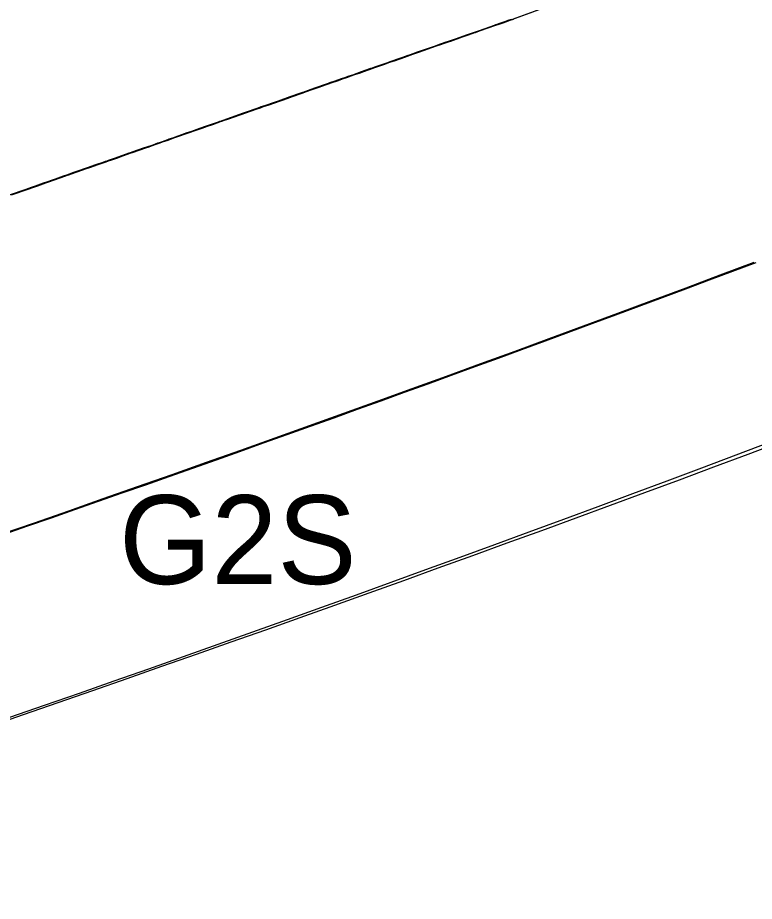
# Model space of a CAD drawing. Extents: x 0 to 512122, y 0 to 6212554.
# Drawn here: x 511630.09 to 511640.46, y 6211385.17 to 6211397.6 of the extents above; entities that cross this region are included whole.
import ezdxf

# ---------------------------------------------------------------- set-up
doc = ezdxf.new("R2010")
doc.units = 0
for name, color, linetype in [('_Paths', 7, 'Continuous'), ('_S1_rabarber', 7, 'Continuous'), ('Tilgængelighed-1', 7, 'Continuous'), ('TV_U_AFM_Symbl_Gul', 7, 'Continuous'), ('TV_U_LYS_Nyx330-Trafiksti-x2', 7, 'Continuous')]:
    doc.layers.add(name, color=color, linetype=linetype)

msp = doc.modelspace()

# ---------------------------------------------------------------- linework, layer by layer
at = {"layer": '_Paths'}
for centre, radius, start, end in [((511490.629, 6211792.585), 425.663, 281.76765, 290.60954), ((511492.968, 6211783.33), 418.626, 281.73735, 290.80486), ((511490.629, 6211792.585), 428.163, 281.76765, 290.60954)]:
    msp.add_arc(centre, radius, start, end, dxfattribs=at)
at = {"layer": '_S1_rabarber'}
for points in [[(511651.978, 6211402.756), (511652.648, 6211403.165), (511654.696, 6211404.619), (511652.478, 6211403.495), (511648.686, 6211401.828), (511637.043, 6211397.572)], [(511648.686, 6211401.828), (511637.066, 6211397.581), (511637.066, 6211397.58), (511637.021, 6211397.564), (511636.972, 6211397.547), (511636.906, 6211397.524), (511636.864, 6211397.509), (511636.849, 6211397.504), (511636.829, 6211397.497), (511636.696, 6211397.45), (511636.602, 6211397.417), (511636.532, 6211397.393), (511636.52, 6211397.389), (511636.433, 6211397.358), (511636.347, 6211397.328), (511636.181, 6211397.27), (511636.149, 6211397.259), (511636.068, 6211397.231), (511636.056, 6211397.226), (511635.983, 6211397.201), (511635.731, 6211397.113), (511635.719, 6211397.108), (511635.648, 6211397.084), (511635.537, 6211397.045), (511635.468, 6211397.021), (511635.39, 6211396.993), (511635.359, 6211396.982), (511635.325, 6211396.971), (511635.242, 6211396.941), (511635.142, 6211396.907), (511635.112, 6211396.896), (511635.089, 6211396.888), (511634.958, 6211396.842), (511634.896, 6211396.82), (511634.832, 6211396.798), (511634.78, 6211396.78), (511634.719, 6211396.758), (511634.673, 6211396.742), (511634.585, 6211396.711), (511634.511, 6211396.686), (511634.5, 6211396.682), (511634.475, 6211396.673), (511634.434, 6211396.659), (511634.327, 6211396.621), (511634.3, 6211396.612), (511634.246, 6211396.593), (511634.136, 6211396.554), (511634.128, 6211396.551), (511634.088, 6211396.537), (511633.953, 6211396.49), (511633.916, 6211396.477), (511633.825, 6211396.445), (511633.771, 6211396.426), (511633.719, 6211396.408), (511633.611, 6211396.37), (511633.545, 6211396.348), (511633.501, 6211396.332), (511633.458, 6211396.317), (511633.363, 6211396.284), (511633.295, 6211396.26), (511633.23, 6211396.237), (511633.123, 6211396.2), (511633.058, 6211396.177), (511632.969, 6211396.146), (511632.961, 6211396.143), (511632.958, 6211396.142), (511632.956, 6211396.141), (511632.83, 6211396.097), (511632.759, 6211396.072), (511632.68, 6211396.044), (511632.568, 6211396.005), (511632.503, 6211395.983), (511632.299, 6211395.911), (511632.249, 6211395.893), (511632.205, 6211395.878), (511632.125, 6211395.85), (511632.088, 6211395.837), (511632.02, 6211395.813), (511631.921, 6211395.779), (511631.902, 6211395.772), (511631.794, 6211395.734), (511631.702, 6211395.702), (511631.684, 6211395.696), (511631.529, 6211395.642), (511631.493, 6211395.629), (511631.395, 6211395.595), (511631.363, 6211395.583), (511631.352, 6211395.58), (511631.317, 6211395.567), (511631.201, 6211395.527), (511631.112, 6211395.495), (511631.041, 6211395.471), (511631.002, 6211395.457), (511630.906, 6211395.424), (511630.805, 6211395.388), (511630.773, 6211395.377), (511630.761, 6211395.373), (511630.59, 6211395.313), (511630.538, 6211395.295), (511630.48, 6211395.274), (511630.366, 6211395.235), (511630.311, 6211395.215), (511630.232, 6211395.188), (511629.998, 6211395.105)], [(511637.066, 6211397.58), (511637.021, 6211397.564), (511636.972, 6211397.547), (511636.906, 6211397.524), (511636.864, 6211397.509), (511636.849, 6211397.504), (511636.829, 6211397.497), (511636.696, 6211397.45), (511636.602, 6211397.417), (511636.532, 6211397.393), (511636.52, 6211397.389), (511636.433, 6211397.358), (511636.347, 6211397.328), (511636.181, 6211397.27), (511636.149, 6211397.259), (511636.068, 6211397.231), (511636.056, 6211397.226), (511635.983, 6211397.201), (511635.731, 6211397.113), (511635.719, 6211397.108), (511635.648, 6211397.084), (511635.537, 6211397.045), (511635.468, 6211397.021), (511635.39, 6211396.993), (511635.359, 6211396.982), (511635.325, 6211396.971), (511635.242, 6211396.941), (511635.142, 6211396.907), (511635.112, 6211396.896), (511635.089, 6211396.888), (511634.958, 6211396.842), (511634.896, 6211396.82), (511634.832, 6211396.798), (511634.78, 6211396.78), (511634.719, 6211396.758), (511634.673, 6211396.742), (511634.585, 6211396.711), (511634.511, 6211396.686), (511634.5, 6211396.682), (511634.475, 6211396.673), (511634.434, 6211396.659), (511634.327, 6211396.621), (511634.3, 6211396.612), (511634.246, 6211396.593), (511634.136, 6211396.554), (511634.128, 6211396.551), (511634.088, 6211396.537), (511633.953, 6211396.49), (511633.916, 6211396.477), (511633.825, 6211396.445), (511633.771, 6211396.426), (511633.719, 6211396.408), (511633.611, 6211396.37), (511633.545, 6211396.348), (511633.501, 6211396.332), (511633.458, 6211396.317), (511633.363, 6211396.284), (511633.295, 6211396.26), (511633.23, 6211396.237), (511633.123, 6211396.2), (511633.058, 6211396.177), (511632.969, 6211396.146), (511632.961, 6211396.143), (511632.958, 6211396.142), (511632.956, 6211396.141), (511632.83, 6211396.097), (511632.759, 6211396.072), (511632.68, 6211396.044), (511632.568, 6211396.005), (511632.503, 6211395.983), (511632.299, 6211395.911), (511632.249, 6211395.893), (511632.205, 6211395.878), (511632.125, 6211395.85), (511632.088, 6211395.837), (511632.02, 6211395.813), (511631.921, 6211395.779), (511631.902, 6211395.772), (511631.794, 6211395.734), (511631.702, 6211395.702), (511631.684, 6211395.696), (511631.529, 6211395.642), (511631.493, 6211395.629), (511631.395, 6211395.595), (511631.363, 6211395.583), (511631.352, 6211395.58), (511631.317, 6211395.567), (511631.201, 6211395.527), (511631.112, 6211395.495), (511631.041, 6211395.471), (511631.002, 6211395.457), (511630.906, 6211395.424), (511630.805, 6211395.388), (511630.773, 6211395.377), (511630.761, 6211395.373), (511630.59, 6211395.313), (511630.538, 6211395.295), (511630.48, 6211395.274), (511630.366, 6211395.235), (511630.311, 6211395.215), (511630.232, 6211395.188), (511629.998, 6211395.105)]]:
    msp.add_lwpolyline(points, dxfattribs=at)
msp.add_arc((511490.655, 6211792.581), 425.663, 287.57872, 290.60954, dxfattribs=at)
msp.add_arc((511490.655, 6211792.581), 425.663, 287.57872, 290.60954, dxfattribs=at)
at = {"layer": 'Tilgængelighed-1'}
msp.add_lwpolyline([(511629.972, 6211395.109), (511630.206, 6211395.192), (511630.285, 6211395.219), (511630.34, 6211395.239), (511630.454, 6211395.278), (511630.512, 6211395.299), (511630.564, 6211395.317), (511630.621, 6211395.337), (511630.735, 6211395.377), (511630.747, 6211395.381), (511630.779, 6211395.392), (511630.88, 6211395.428), (511630.976, 6211395.461), (511631.015, 6211395.475), (511631.086, 6211395.499), (511631.175, 6211395.531), (511631.204, 6211395.541), (511631.291, 6211395.571), (511631.326, 6211395.584), (511631.337, 6211395.587), (511631.369, 6211395.599), (511631.467, 6211395.633), (511631.503, 6211395.646), (511631.658, 6211395.7), (511631.676, 6211395.706), (511631.768, 6211395.738), (511631.876, 6211395.776), (511631.895, 6211395.783), (511631.994, 6211395.817), (511632.062, 6211395.841), (511632.099, 6211395.854), (511632.179, 6211395.882), (511632.223, 6211395.897), (511632.273, 6211395.915), (511632.477, 6211395.987), (511632.542, 6211396.009), (511632.654, 6211396.048), (511632.733, 6211396.076), (511632.804, 6211396.101), (511632.93, 6211396.145), (511632.932, 6211396.146), (511632.935, 6211396.147), (511632.943, 6211396.15), (511633.032, 6211396.181), (511633.097, 6211396.204), (511633.204, 6211396.241), (511633.269, 6211396.264), (511633.337, 6211396.288), (511633.432, 6211396.321), (511633.475, 6211396.336), (511633.519, 6211396.352), (511633.585, 6211396.374), (511633.693, 6211396.412), (511633.745, 6211396.43), (511633.799, 6211396.449), (511633.89, 6211396.481), (511633.927, 6211396.494), (511634.062, 6211396.541), (511634.102, 6211396.555), (511634.11, 6211396.558), (511634.22, 6211396.597), (511634.274, 6211396.616), (511634.301, 6211396.625), (511634.408, 6211396.663), (511634.449, 6211396.677), (511634.474, 6211396.686), (511634.485, 6211396.69), (511634.559, 6211396.715), (511634.647, 6211396.746), (511634.693, 6211396.762), (511634.754, 6211396.784), (511634.806, 6211396.802), (511634.87, 6211396.824), (511634.932, 6211396.846), (511635.063, 6211396.892), (511635.086, 6211396.9), (511635.116, 6211396.911), (511635.216, 6211396.945), (511635.299, 6211396.975), (511635.333, 6211396.986), (511635.364, 6211396.997), (511635.442, 6211397.025), (511635.511, 6211397.049), (511635.585, 6211397.075), (511635.622, 6211397.088), (511635.693, 6211397.112), (511635.705, 6211397.117), (511635.957, 6211397.205), (511636.03, 6211397.23), (511636.042, 6211397.235), (511636.123, 6211397.263), (511636.155, 6211397.274), (511636.238, 6211397.303), (511636.321, 6211397.332), (511636.407, 6211397.362), (511636.494, 6211397.393), (511636.506, 6211397.397), (511636.576, 6211397.421), (511636.67, 6211397.454), (511636.803, 6211397.501), (511636.823, 6211397.508), (511636.838, 6211397.513), (511636.88, 6211397.528), (511636.946, 6211397.551), (511636.995, 6211397.568), (511637.04, 6211397.584)], dxfattribs=at)
at = {"layer": 'TV_U_LYS_Nyx330-Trafiksti-x2'}
msp.add_lwpolyline([(511629.972, 6211395.109), (511630.206, 6211395.192), (511630.285, 6211395.219), (511630.34, 6211395.239), (511630.454, 6211395.278), (511630.512, 6211395.299), (511630.564, 6211395.317), (511630.621, 6211395.337), (511630.735, 6211395.377), (511630.747, 6211395.381), (511630.779, 6211395.392), (511630.88, 6211395.428), (511630.976, 6211395.461), (511631.015, 6211395.475), (511631.086, 6211395.499), (511631.175, 6211395.531), (511631.204, 6211395.541), (511631.291, 6211395.571), (511631.326, 6211395.584), (511631.337, 6211395.587), (511631.369, 6211395.599), (511631.467, 6211395.633), (511631.503, 6211395.646), (511631.658, 6211395.7), (511631.676, 6211395.706), (511631.768, 6211395.738), (511631.876, 6211395.776), (511631.895, 6211395.783), (511631.994, 6211395.817), (511632.062, 6211395.841), (511632.099, 6211395.854), (511632.179, 6211395.882), (511632.223, 6211395.897), (511632.273, 6211395.915), (511632.477, 6211395.987), (511632.542, 6211396.009), (511632.654, 6211396.048), (511632.733, 6211396.076), (511632.804, 6211396.101), (511632.93, 6211396.145), (511632.932, 6211396.146), (511632.935, 6211396.147), (511632.943, 6211396.15), (511633.032, 6211396.181), (511633.097, 6211396.204), (511633.204, 6211396.241), (511633.269, 6211396.264), (511633.337, 6211396.288), (511633.432, 6211396.321), (511633.475, 6211396.336), (511633.519, 6211396.352), (511633.585, 6211396.374), (511633.693, 6211396.412), (511633.745, 6211396.43), (511633.799, 6211396.449), (511633.89, 6211396.481), (511633.927, 6211396.494), (511634.062, 6211396.541), (511634.102, 6211396.555), (511634.11, 6211396.558), (511634.22, 6211396.597), (511634.274, 6211396.616), (511634.301, 6211396.625), (511634.408, 6211396.663), (511634.449, 6211396.677), (511634.474, 6211396.686), (511634.485, 6211396.69), (511634.559, 6211396.715), (511634.647, 6211396.746), (511634.693, 6211396.762), (511634.754, 6211396.784), (511634.806, 6211396.802), (511634.87, 6211396.824), (511634.932, 6211396.846), (511635.063, 6211396.892), (511635.086, 6211396.9), (511635.116, 6211396.911), (511635.216, 6211396.945), (511635.299, 6211396.975), (511635.333, 6211396.986), (511635.364, 6211396.997), (511635.442, 6211397.025), (511635.511, 6211397.049), (511635.585, 6211397.075), (511635.622, 6211397.088), (511635.693, 6211397.112), (511635.705, 6211397.117), (511635.957, 6211397.205), (511636.03, 6211397.23), (511636.042, 6211397.235), (511636.123, 6211397.263), (511636.155, 6211397.274), (511636.238, 6211397.303), (511636.321, 6211397.332), (511636.407, 6211397.362), (511636.494, 6211397.393), (511636.506, 6211397.397), (511636.576, 6211397.421), (511636.67, 6211397.454), (511636.803, 6211397.501), (511636.823, 6211397.508), (511636.838, 6211397.513), (511636.88, 6211397.528), (511636.946, 6211397.551), (511636.995, 6211397.568), (511637.04, 6211397.584)], dxfattribs=at)

# ---------------------------------------------------------------- texts
at = {"layer": 'TV_U_AFM_Symbl_Gul'}
msp.add_text('G2S', height=1.25, dxfattribs=at).set_placement((511631.516, 6211389.634))

doc.saveas('drawing.dxf')
